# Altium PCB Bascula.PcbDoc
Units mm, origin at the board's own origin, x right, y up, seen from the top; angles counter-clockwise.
Board outline 60.45 x 51.82 mm, 2 copper layers (Top Layer, Bottom Layer); 12 components, 14 nets, 81 pads, 0 vias.
Unrouted connection lines stored in the file: 3.
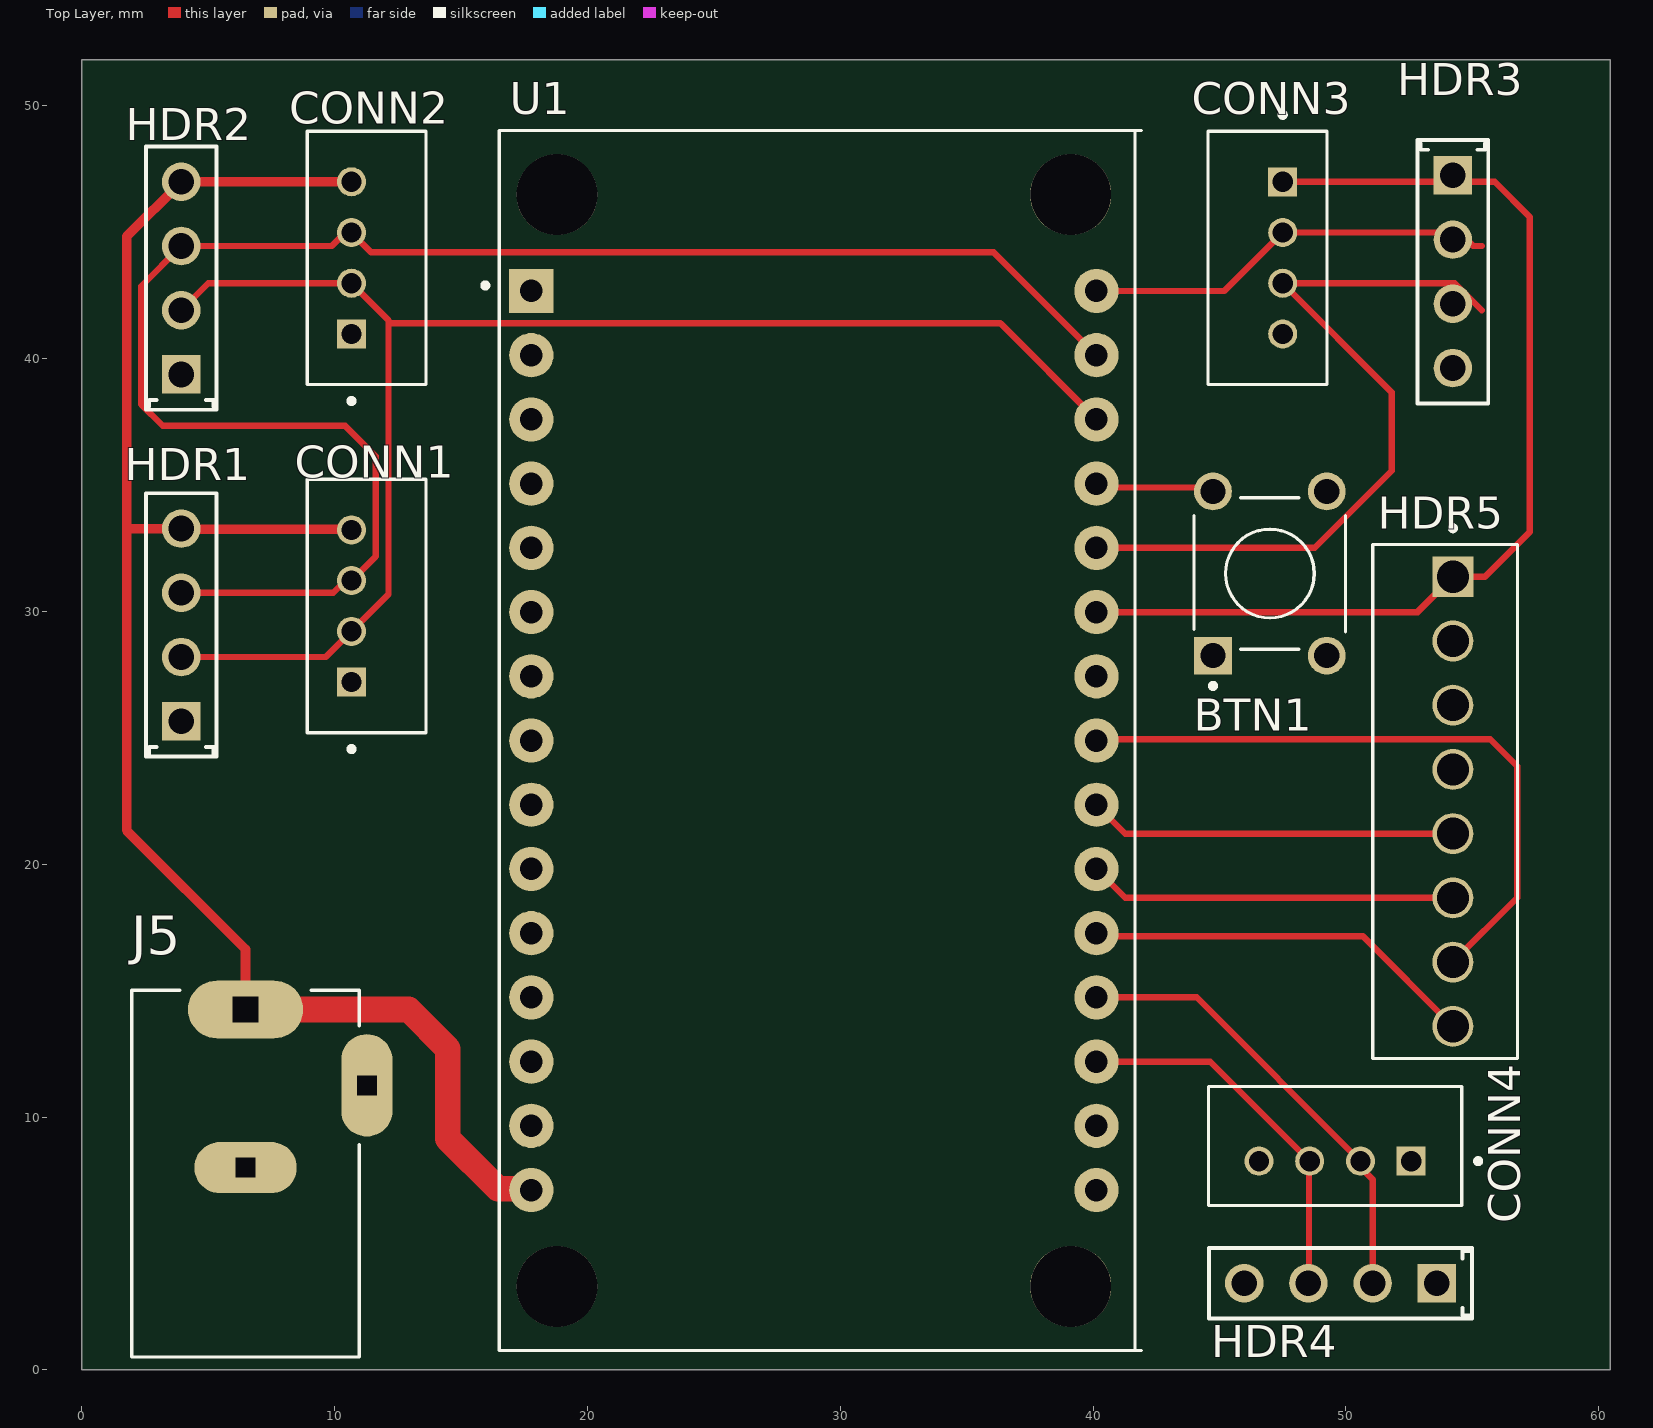
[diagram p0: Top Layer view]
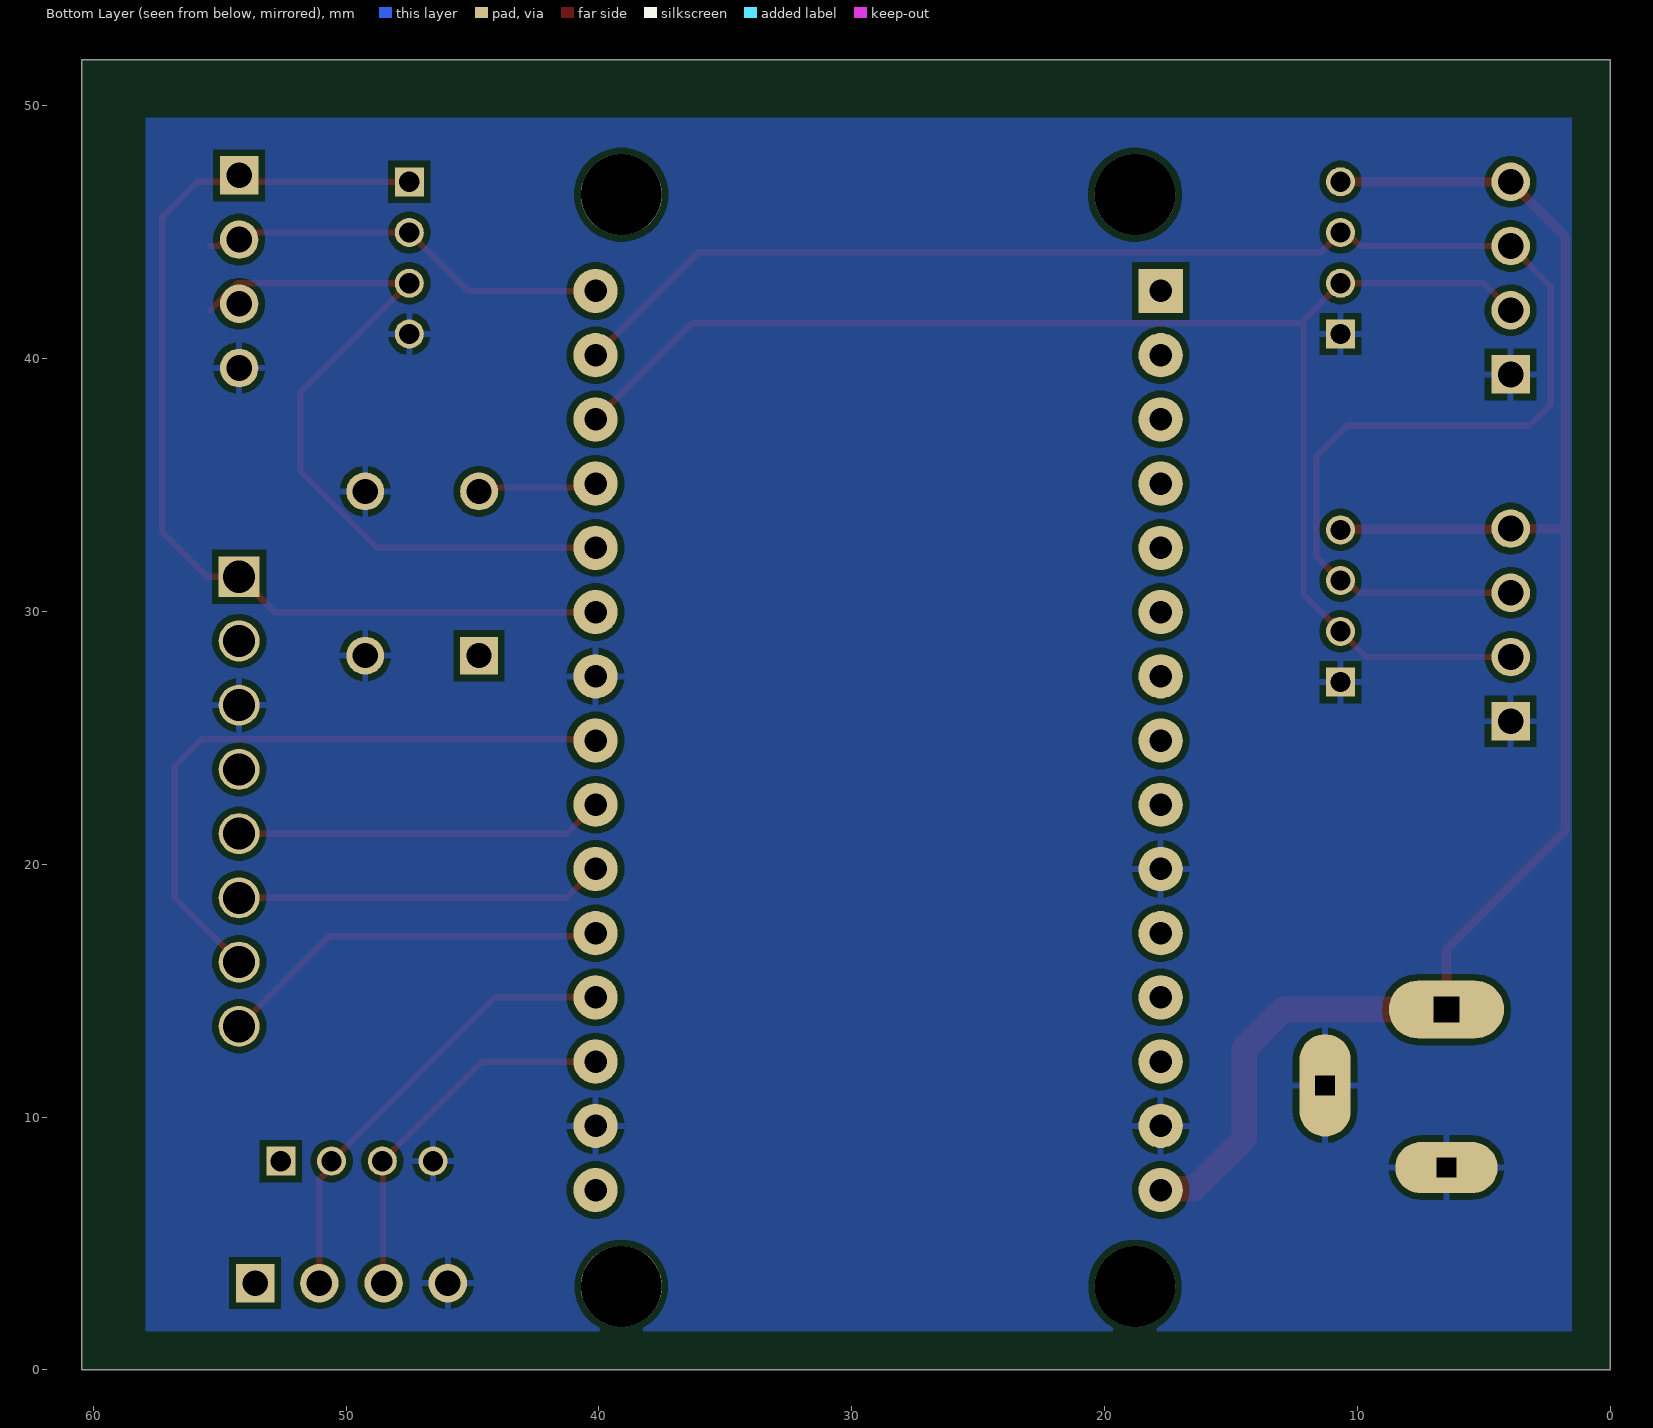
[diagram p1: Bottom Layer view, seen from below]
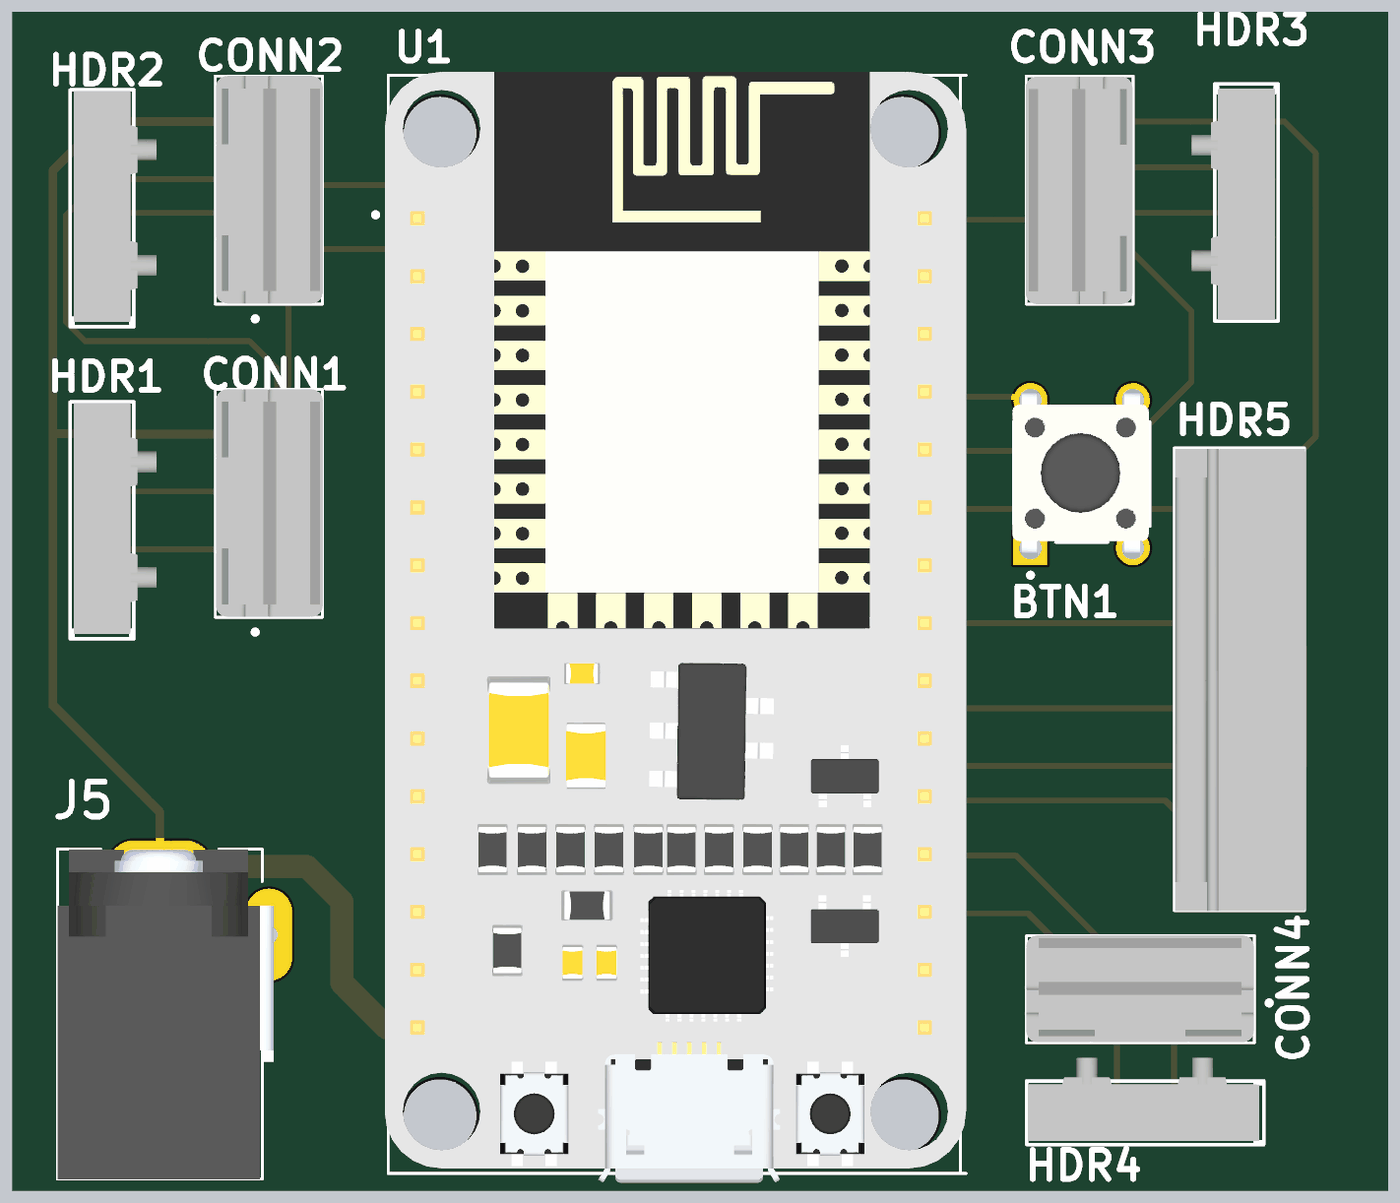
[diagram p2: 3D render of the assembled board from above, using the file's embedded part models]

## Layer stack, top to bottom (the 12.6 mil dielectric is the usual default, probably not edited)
Top Solder: solder mask 0.0102, Solder Resist, Dk 3.5
Top Layer: signal copper 0.0356
Dielectric 1: dielectric 0.32, FR-4, Dk 4.8
Bottom Layer: signal copper 0.0356
Bottom Solder: solder mask 0.0102, Solder Resist, Dk 3.5

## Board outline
0,0 0,51.816 60.452,51.816 60.452,0

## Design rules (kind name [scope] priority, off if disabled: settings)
Clearance [All] p1: gap=0.254 ignorepadtopadclearanceinfootprint=FALSE except(0: Arc-Hole Track-Hole SMDPad-Hole THPad-Hole Via-Hole Fill-Hole Poly-Hole Region-Hole Text-Hole)
PolygonConnect [All] p1: connectstyle=Relief reliefconductorwidth=0.254 reliefentries=4 polygonreliefangle="90 Angle" airgapwidth=0.254
RoutingVias [All] p1: holewidth=0.711 width=1.27 viastyle="Through Hole" minholewidth=0.711 minwidth=1.27 maxholewidth=0.711 maxwidth=1.27
SolderMaskExpansion [All] p1: expansion=0.102 istentingtop=FALSE
Width [All] p1: maxlimit=1.27 minlimit=0.254 preferedwidth=0.254
30 further rules are at their usual default settings.

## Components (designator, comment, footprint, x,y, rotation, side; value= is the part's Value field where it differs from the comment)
BTN1 "N-O Button" 1825910-6 46.99,31.496 r90 top
CONN1 "4 Pin connector" 440054-4 10.668,27.203 r90 top locked
CONN2 "4 Pin connector" 440054-4 10.668,40.97 r90 top locked
CONN3 "4 Pin connector" 440054-4 47.498,46.99 r270 top locked
CONN4 "4 Pin connector" 440054-4 52.578,8.255 r180 top locked
HDR1 "CONN HEADER VERT 4POS 2.54MM" 825433-4 3.937,25.654 r90 top locked
HDR2 "CONN HEADER VERT 4POS 2.54MM" 825433-4 3.937,39.37 r90 top locked
HDR3 "CONN HEADER VERT 4POS 2.54MM" 825433-4 54.229,47.244 r270 top locked
HDR4 "CONN HEADER VERT 4POS 2.54MM" 825433-4 53.594,3.429 r180 top locked
HDR5 "CONN HEADER VERT 8POS 2.54MM" 640454-8 54.229,31.369 r270 top locked
J5 "CONN PWR JACK 2.5X5.5MM SOLDER" RAPC712X 6.477,8.001 r0 top
U1 "NodeMCU - ESP8266" ZC563900 29.21,24.892 r0 top locked

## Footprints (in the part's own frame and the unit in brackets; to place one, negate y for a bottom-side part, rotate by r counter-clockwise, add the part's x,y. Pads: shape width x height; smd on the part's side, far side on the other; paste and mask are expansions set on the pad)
440054-4 [mm] "4 pin male connector for PCB"
  rect 1.15x1.15 hole 0.8: 1(0,0)
  round 1.15 hole 0.8: 2(2.007,0) 3(4.013,0) 4(6.02,0)
  silkscreen extent -2.75,-2.95 8.02,1.75, body extent -1.98,-2.97 8.02,1.73, height 6.06
640454-8 [mm] "8 pin male header connector 2.54MM"
  rect 1.62x1.62 hole 1.27: 1(0,0)
  round 1.62 hole 1.27: 2(2.54,0) 3(5.08,0) 4(7.62,0) 5(10.16,0) 6(12.7,0) 7(15.24,0) 8(17.78,0)
  silkscreen extent -2.02,-3.17 19.05,2.55, body extent -1.24,-3.13 19.08,2.59, height 10.09
825433-4 [mil] "HDR_1X4_0.100\""
  rect 60x60 hole 40 mask+0: 1(0,0)
  round 60 hole 40 mask+0: 2(100,0) 3(200,0) 4(300,0)
  silkscreen extent -55,-55 355,55, body extent -47,-95 353,49, height 375
1825910-6 [mm] "NO Button"
  rect 1.498x1.498 hole 0.99: 1(-3.25,2.25)
  round 1.498 hole 0.99: 2(3.25,2.25) 3(-3.25,-2.25) 4(3.25,-2.25)
  silkscreen extent -4.54,-3 3,3, body extent -3.85,-2.94 3.95,3.05, height 5.01
RAPC712X [mm] "Power Jack Barrel TH"
  oval 4.56x2.28 hole 1.02 square: PIN(0,6.25)
  oval 2.025x4.05 hole 0.76 square: SHUNT(4.8,3.25)
  oval 4.05x2.025 hole 0.76 square: SLEEVE(0,0)
  silkscreen extent -4.5,-7.49 4.5,7.01, body extent -4.5,-7.49 5,6.99, height 10.93
ZC563900 [mil] "NodeMCU ESP8266"
  rect 69x69 hole 35: 1(-450,700)
  round 69 hole 35: 2(-450,600) 3(-450,500) 4(-450,400) 5(-450,300) 6(-450,200) 7(-450,100) 8(-450,0) 9(-450,-100) 10(-450,-200) 11(-450,-300) 12(-450,-400) 13(-450,-500) 14(-450,-600) 15(-450,-700) 16(430,-700) 17(430,-600) 18(430,-500) 19(430,-400) 20(430,-300) 21(430,-200) 22(430,-100) 23(430,0) 24(430,100) 25(430,200) 26(430,300) 27(430,400) 28(430,500) 29(430,600) 30(430,700)
  round 125.98 hole 125.98 unplated: ""(-410,-850) ""(-410,850) ""(390,-850) ""(390,850)
  silkscreen extent -526,-950 500,950, body extent -506,-966 500,956, height 305

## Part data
BTN1: library part 1825910-6, "Interruptores táctiles SPST-NO (Normalmente abierto) Activación superior Orificio pasante. SWITCH TACTILE SPST-NO 0.05A 24V", Contact_Current_Rating="50 mA", Package=None, Supplier Part Number 1=450-1650-ND
CONN1 CONN2 CONN3 CONN4: library part 440054-4, "Cabezal de conector Orificio pasante 4 posiciones 0.079\" (2.00mm).  / Complementario con 1735447-4.", Package=None, Supplier Part Number 1=A100036-ND
HDR1 HDR2 HDR3 HDR4: library part 825433-4, "Cabezal de conector Orificio pasante 4 posiciones 0.100\" (2.54mm)", Color=Green, Contact Current Rating=5A, Current Rating=3A, Flammability Rating="UL94 V-0", High Temperature Housing=No, Manufacturer="TE Connectivity", Max Operating Temperature=105°C, Min Operating Temperature=-65°C, Package Quantity=1200, Supplier Part Number 1=99K0796
HDR5: library part 640454-8, "Cabezal de conector Orificio pasante 8 posiciones 0.100\" (2.54mm). / Complementario con 3-644540-8.", Color=Natural,Beige,White, Contact Current Rating=5A, Contact Resistance=6mR, Flammability Rating="UL94 V-0", Housing Color=Natural, Manufacturer="TE Connectivity", Max Operating Temperature=221°C, Max Voltage Rating (AC)=250V, Min Operating Temperature=-67°C, Package=None, Package Quantity=1, Supplier Part Number 1=A19435-ND
J5: library part RAPC712X, "Conn DC Power PL 2 POS Solder RA Thru-Hole 3 Terminal 1 Port Bulk", Color=Black, Current Rating=5A, Flammability Rating="UL94 V-0", Insulation Resistance=30MR, Manufacturer=Switchcraft, Package=None, Package Quantity=2500, Supplier Part Number 1=SC237-ND
U1: library part ZC563900, "NodeMcu Lua ESP8266 WIFI Internet of Things Network Development Module Board", Manufacturer_Name=YKS, Package=None, Supplier Part Number 1=713-113990105

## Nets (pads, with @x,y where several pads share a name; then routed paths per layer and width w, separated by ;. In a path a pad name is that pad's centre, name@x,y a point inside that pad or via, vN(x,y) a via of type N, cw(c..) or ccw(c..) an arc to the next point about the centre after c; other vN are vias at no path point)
3V3: CONN3.1 HDR3.1 HDR5.1 U1.11 U1.16 U1.25 | length 41.3
  Top Layer w0.254: U1.25 52.832,29.972 HDR5.1 55.499,31.369 57.277,33.147 57.277,45.593 55.88,46.99 54.229,46.99 CONN3.1
5V: CONN1.4 CONN2.4 HDR1.4 HDR2.4 J5.PIN U1.15 | length 67.6
  Top Layer w0.381: J5.PIN 6.477,16.637 1.778,21.336 1.778,33.274 ; CONN1.4 10.643,33.249 3.962,33.249 HDR1.4 1.778,33.274 ; CONN2.4 HDR2.4 1.778,44.831 1.778,33.274
  Top Layer w1.016: J5.PIN 12.927,14.251 14.478,12.7 14.478,9.144 16.464,7.158 17.734,7.158 U1.15
CLK: CONN3.2 HDR3.2 U1.30 | length 16.4
  Top Layer w0.254: U1.30 45.187,42.672 CONN3.2 54.495,44.983 55.028,44.45 55.372,44.45
DATA: CONN3.3 HDR3.3 U1.26 | length 30.5
  Top Layer w0.254: U1.26 48.768,32.512 51.816,35.56 51.816,38.659 CONN3.3 54.305,42.977 55.372,41.91
GND: BTN1.3 BTN1.4 CONN1.1 CONN2.1 CONN3.4 CONN4.4 HDR1.1 HDR2.1 HDR3.4 HDR4.4 HDR5.3 J5.SHUNT J5.SLEEVE U1.10 U1.14 U1.17 U1.24
MISO: HDR5.5 U1.22 | length 14.6
  Top Layer w0.254: U1.22 41.275,21.209 HDR5.5
MOSI: HDR5.6 U1.21 | length 14.6
  Top Layer w0.254: U1.21 41.275,18.669 HDR5.6
NetBTN1_1: BTN1.1 BTN1.2 U1.27 | length 4.7
  Top Layer w0.254: U1.27 40.285,34.899 44.587,34.899 BTN1.2
RX: CONN4.2 HDR4.2 U1.19 | length 18.1
  Top Layer w0.254: U1.19 44.094,14.732 CONN4.2 50.571,8.013 51.054,7.53 HDR4.2
SCL: CONN1.3 CONN2.3 HDR1.3 HDR2.3 U1.29 | length 67.7
  Top Layer w0.254: HDR1.3 9.944,30.734 10.426,31.216 CONN1.3 11.624,32.172 11.624,36.128 10.414,37.338 3.197,37.338 2.349,38.185 2.349,42.862 HDR2.3 9.893,44.45 10.426,44.983 CONN2.3 11.455,44.196 36.068,44.196 U1.29
SCLK: HDR5.7 U1.23 | length 25.9
  Top Layer w0.254: U1.23 40.18,24.94 55.705,24.94 56.769,23.876 56.769,18.669 HDR5.7
SDA: CONN1.2 CONN2.2 HDR1.2 HDR2.2 U1.28 | length 58.9
  Top Layer w0.254: HDR1.2 9.652,28.194 CONN1.2 12.132,30.674 12.132,41.513 CONN2.2 5.004,42.977 HDR2.2 ; 12.132,41.389 36.335,41.389 U1.28
SS: HDR5.8 U1.20 | length 15.6
  Top Layer w0.254: U1.20 40.259,17.145 50.673,17.145 HDR5.8
TX: CONN4.3 HDR4.3 U1.18 | length 14.9
  Top Layer w0.254: U1.18 44.628,12.192 CONN4.3 48.539,8.229 48.539,3.454 HDR4.3
pads on no net: CONN4.1 HDR4.1 HDR5.2 HDR5.4 U1. U1.1 U1.2 U1.3 U1.4 U1.5 U1.6 U1.7 U1.8 U1.9 U1.12 U1.13

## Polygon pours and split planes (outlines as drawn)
GND on Bottom Layer "GND_L02_P000" (solid, pour order 0): 57.912,49.53 57.912,1.524 1.524,1.524 1.524,49.53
